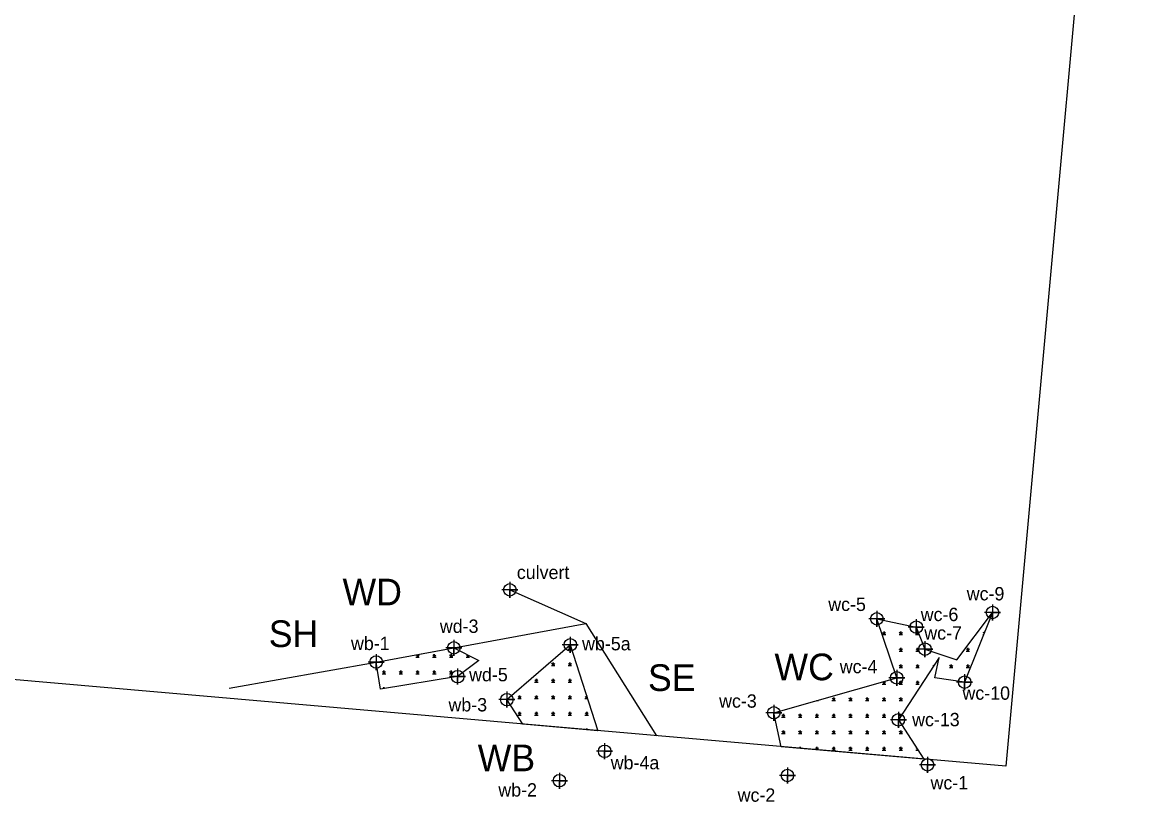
# Model space of a CAD drawing. Extents: x 1637473 to 1644249, y 841388 to 844031.
# Drawn here: x 1643834.8 to 1644249.1, y 841860 to 842152.5 of the extents above; entities that cross this region are included whole.
import ezdxf

# ---------------------------------------------------------------- set-up
doc = ezdxf.new("R2010")
doc.units = 0
for name, color, linetype in [('Default', 7, 'Continuous'), ('Exist Environmental Wetland Boundary', 7, 'Continuous'), ('Exist Environmental Wetland Boundary Cogo Number', 7, 'Continuous'), ('Exist Environmental Wetland Boundary Cogo Point CELL', 7, 'Continuous'), ('Exist Environmental Wetland Boundary Text', 7, 'Continuous'), ('Exist Hydro Jurisdictional Stream or Body of Water Mitigable', 7, 'Continuous'), ('Exist Hydro Jurisdictional Stream or Body of Water Mitigable Cogo Number', 7, 'Continuous'), ('Exist Hydro Jurisdictional Stream or Body of Water Mitigable Cogo Point CELL', 7, 'Continuous'), ('Exist Hydro Jurisdictional Stream or Body of Water Mitigable Text', 7, 'Continuous')]:
    doc.layers.add(name, color=color, linetype=linetype)

msp = doc.modelspace()

# ---------------------------------------------------------------- linework, layer by layer
at = {"layer": 'Default'}
msp.add_lwpolyline([(1643420.44, 842444.99), (1644249.14, 842372.65), (1644203.72, 841873.41), (1643376.84, 841945.6)], dxfattribs=at)
at = {"layer": 'Exist Environmental Wetland Boundary'}
for points in [[(1644198.76, 841931.06), (1644188.29, 841904.96), (1644177.17, 841906.58), (1644178.79, 841914.22), (1644163.45, 841890.81), (1644172.99, 841876.09), (1644119.48, 841880.76), (1644116.71, 841893.48), (1644162.8, 841906.58), (1644155.38, 841928.73), (1644170.15, 841925.61), (1644173.42, 841917.33), (1644185.39, 841913.29)], [(1644040.4, 841918.96), (1644050.78, 841886.76), (1644022.57, 841889.22), (1644016.62, 841898.41)], [(1643998.17, 841907.02), (1643969.25, 841902.37), (1643967.6, 841912.49), (1643996.74, 841917.83), (1644006.11, 841913.03)]]:
    msp.add_lwpolyline(points, close=True, dxfattribs=at)
at = {"layer": 'Exist Environmental Wetland Boundary Cogo Point CELL'}
for points in [[(1644155.38, 841931.73), (1644155.38, 841925.73), (1644155.38, 841928.73), (1644158.38, 841928.73), (1644152.38, 841928.73)], [(1644198.76, 841934.06), (1644198.76, 841928.06), (1644198.76, 841931.06), (1644201.76, 841931.06), (1644195.76, 841931.06)], [(1644170.15, 841928.61), (1644170.15, 841922.61), (1644170.15, 841925.61), (1644173.15, 841925.61), (1644167.15, 841925.61)], [(1643996.72, 841920.84), (1643996.72, 841914.84), (1643996.72, 841917.84), (1643999.72, 841917.84), (1643993.72, 841917.84)], [(1644040.4, 841921.96), (1644040.4, 841915.96), (1644040.4, 841918.96), (1644043.4, 841918.96), (1644037.4, 841918.96)], [(1644173.42, 841920.33), (1644173.42, 841914.33), (1644173.42, 841917.33), (1644176.42, 841917.33), (1644170.42, 841917.33)], [(1643967.6, 841915.49), (1643967.6, 841909.49), (1643967.6, 841912.49), (1643970.6, 841912.49), (1643964.6, 841912.49)], [(1643998.17, 841910.02), (1643998.17, 841904.02), (1643998.17, 841907.02), (1644001.17, 841907.02), (1643995.17, 841907.02)], [(1644162.8, 841909.58), (1644162.8, 841903.58), (1644162.8, 841906.58), (1644165.8, 841906.58), (1644159.8, 841906.58)], [(1644188.29, 841907.96), (1644188.29, 841901.96), (1644188.29, 841904.96), (1644191.29, 841904.96), (1644185.29, 841904.96)], [(1644016.62, 841901.41), (1644016.62, 841895.41), (1644016.62, 841898.41), (1644019.62, 841898.41), (1644013.62, 841898.41)], [(1644116.71, 841896.48), (1644116.71, 841890.48), (1644116.71, 841893.48), (1644119.71, 841893.48), (1644113.71, 841893.48)], [(1644163.45, 841893.81), (1644163.45, 841887.81), (1644163.45, 841890.81), (1644166.45, 841890.81), (1644160.45, 841890.81)], [(1644053.27, 841882.02), (1644053.27, 841876.02), (1644053.27, 841879.02), (1644056.27, 841879.02), (1644050.27, 841879.02)], [(1644174.37, 841876.97), (1644174.37, 841870.97), (1644174.37, 841873.97), (1644177.37, 841873.97), (1644171.37, 841873.97)], [(1644036.33, 841870.99), (1644036.33, 841864.99), (1644036.33, 841867.99), (1644039.33, 841867.99), (1644033.33, 841867.99)], [(1644121.83, 841872.93), (1644121.83, 841866.93), (1644121.83, 841869.93), (1644124.83, 841869.93), (1644118.83, 841869.93)]]:
    msp.add_lwpolyline(points, dxfattribs=at)
for centre in [(1644155.38, 841928.73), (1644198.76, 841931.06), (1644170.15, 841925.61), (1643996.72, 841917.84), (1644040.4, 841918.96), (1644173.42, 841917.33), (1643967.6, 841912.49), (1643998.17, 841907.02), (1644162.8, 841906.58), (1644188.29, 841904.96), (1644016.62, 841898.41), (1644116.71, 841893.48), (1644163.45, 841890.81), (1644053.27, 841879.02), (1644174.37, 841873.97), (1644036.33, 841867.99), (1644121.83, 841869.93)]:
    msp.add_circle(centre, 2.34, dxfattribs=at)
at = {"layer": 'Exist Hydro Jurisdictional Stream or Body of Water Mitigable'}
for p, q in [((1644195.15, 841922.78), (1644195.44, 841922.78)), ((1644176.28, 841910.42), (1644176.3, 841910.42)), ((1644163.7, 841891.87), (1644164.14, 841891.87))]:
    msp.add_line(p, q, dxfattribs=at)
for points in [[(1644017.71, 841939.6), (1644046.25, 841926.95), (1644072.77, 841884.84)], [(1643912.46, 841902.74), (1643967.6, 841912.49), (1644046.25, 841926.95)], [(1644157.41, 841922.78), (1644158.06, 841922.78), (1644158.06, 841923.97), (1644158.06, 841922.78), (1644158.7, 841922.78)], [(1644163.7, 841922.78), (1644164.35, 841922.78), (1644164.35, 841923.97), (1644164.35, 841922.78), (1644164.99, 841922.78)], [(1644169.99, 841922.78), (1644170.64, 841922.78), (1644170.64, 841923.97), (1644170.64, 841922.78), (1644171.27, 841922.78)], [(1644195.8, 841923.68), (1644195.8, 841923.97), (1644195.8, 841923.68)], [(1643982.47, 841914.31), (1643983.12, 841914.31), (1643983.12, 841915.34)], [(1643983.12, 841915.34), (1643983.12, 841914.31), (1643983.76, 841914.31)], [(1643988.76, 841914.31), (1643989.41, 841914.31), (1643989.41, 841915.49), (1643989.41, 841914.31), (1643990.05, 841914.31)], [(1643995.05, 841914.31), (1643995.7, 841914.31), (1643995.7, 841915.49), (1643995.7, 841914.31), (1643996.34, 841914.31)], [(1644001.34, 841914.31), (1644001.99, 841914.31), (1644001.99, 841915.14)], [(1644001.99, 841915.14), (1644001.99, 841914.31), (1644002.63, 841914.31)], [(1644039.62, 841917.33), (1644040.26, 841917.33), (1644040.26, 841918.52), (1644040.26, 841917.33), (1644040.91, 841917.33)], [(1644163.7, 841916.6), (1644164.35, 841916.6), (1644164.35, 841917.78), (1644164.35, 841916.6), (1644164.99, 841916.6)], [(1644169.99, 841916.6), (1644170.64, 841916.6), (1644170.64, 841917.78), (1644170.64, 841916.6), (1644171.28, 841916.6)], [(1644188.86, 841916.6), (1644189.51, 841916.6), (1644189.51, 841917.78), (1644189.51, 841916.6), (1644190.15, 841916.6)], [(1644033.33, 841911.15), (1644033.97, 841911.15), (1644033.97, 841912.33), (1644033.97, 841911.15), (1644034.62, 841911.15)], [(1644039.62, 841911.15), (1644040.26, 841911.15), (1644040.26, 841912.33), (1644040.26, 841911.15), (1644040.91, 841911.15)], [(1644163.7, 841910.42), (1644164.35, 841910.42), (1644164.35, 841911.6), (1644164.35, 841910.42), (1644164.99, 841910.42)], [(1644169.99, 841910.42), (1644170.64, 841910.42), (1644170.64, 841911.6), (1644170.64, 841910.42), (1644171.28, 841910.42)], [(1644176.93, 841911.38), (1644176.93, 841911.6), (1644176.93, 841911.38)], [(1644182.57, 841910.42), (1644183.22, 841910.42), (1644183.22, 841911.6), (1644183.22, 841910.42), (1644183.86, 841910.42)], [(1644188.86, 841910.42), (1644189.51, 841910.42), (1644189.51, 841911.6), (1644189.51, 841910.42), (1644190.15, 841910.42)], [(1643969.89, 841908.12), (1643970.54, 841908.12), (1643970.54, 841909.31), (1643970.54, 841908.12), (1643971.18, 841908.12)], [(1643976.18, 841908.12), (1643976.83, 841908.12), (1643976.83, 841909.31), (1643976.83, 841908.12), (1643977.47, 841908.12)], [(1643982.47, 841908.12), (1643983.12, 841908.12), (1643983.12, 841909.31), (1643983.12, 841908.12), (1643983.76, 841908.12)], [(1643988.76, 841908.12), (1643989.41, 841908.12), (1643989.41, 841909.31), (1643989.41, 841908.12), (1643990.05, 841908.12)], [(1643995.05, 841908.12), (1643995.7, 841908.12), (1643995.7, 841909.31), (1643995.7, 841908.12), (1643996.34, 841908.12)], [(1644027.04, 841904.97), (1644027.68, 841904.97), (1644027.68, 841906.15), (1644027.68, 841904.97), (1644028.33, 841904.97)], [(1644033.33, 841904.97), (1644033.97, 841904.97), (1644033.97, 841906.15), (1644033.97, 841904.97), (1644034.62, 841904.97)], [(1644039.62, 841904.97), (1644040.26, 841904.97), (1644040.26, 841906.15), (1644040.26, 841904.97), (1644040.91, 841904.97)], [(1643970.54, 841902.57), (1643970.54, 841903.12), (1643970.54, 841902.57)], [(1644157.41, 841904.23), (1644158.06, 841904.23), (1644158.06, 841905.24)], [(1644158.06, 841905.24), (1644158.06, 841904.23), (1644158.7, 841904.23)], [(1644163.7, 841904.23), (1644164.35, 841904.23), (1644164.35, 841905.42), (1644164.35, 841904.23), (1644164.99, 841904.23)], [(1644169.99, 841904.23), (1644170.64, 841904.23), (1644170.64, 841905.42), (1644170.64, 841904.23), (1644171.28, 841904.23)], [(1644020.75, 841898.78), (1644021.39, 841898.78), (1644021.39, 841899.97), (1644021.39, 841898.78), (1644022.04, 841898.78)], [(1644027.04, 841898.78), (1644027.68, 841898.78), (1644027.68, 841899.97), (1644027.68, 841898.78), (1644028.33, 841898.78)], [(1644033.33, 841898.78), (1644033.97, 841898.78), (1644033.97, 841899.97), (1644033.97, 841898.78), (1644034.62, 841898.78)], [(1644039.62, 841898.78), (1644040.26, 841898.78), (1644040.26, 841899.97), (1644040.26, 841898.78), (1644040.91, 841898.78)], [(1644045.91, 841898.78), (1644046.55, 841898.78), (1644046.55, 841899.87)], [(1644046.55, 841899.87), (1644046.55, 841898.78), (1644046.9, 841898.78)], [(1644132.78, 841898.05), (1644132.9, 841898.05), (1644132.9, 841898.08)], [(1644132.9, 841898.08), (1644132.9, 841898.05), (1644133.54, 841898.05)], [(1644138.54, 841898.05), (1644139.19, 841898.05), (1644139.19, 841899.23), (1644139.19, 841898.05), (1644139.83, 841898.05)], [(1644144.83, 841898.05), (1644145.48, 841898.05), (1644145.48, 841899.23), (1644145.48, 841898.05), (1644146.12, 841898.05)], [(1644151.12, 841898.05), (1644151.77, 841898.05), (1644151.77, 841899.23), (1644151.77, 841898.05), (1644152.41, 841898.05)], [(1644157.41, 841898.05), (1644158.06, 841898.05), (1644158.06, 841899.23), (1644158.06, 841898.05), (1644158.7, 841898.05)], [(1644163.7, 841898.05), (1644164.35, 841898.05), (1644164.35, 841899.23), (1644164.35, 841898.05), (1644164.99, 841898.05)], [(1644020.75, 841892.6), (1644021.39, 841892.6), (1644021.39, 841893.78), (1644021.39, 841892.6), (1644022.04, 841892.6)], [(1644027.04, 841892.6), (1644027.68, 841892.6), (1644027.68, 841893.78), (1644027.68, 841892.6), (1644028.33, 841892.6)], [(1644033.33, 841892.6), (1644033.97, 841892.6), (1644033.97, 841893.78), (1644033.97, 841892.6), (1644034.62, 841892.6)], [(1644039.62, 841892.6), (1644040.26, 841892.6), (1644040.26, 841893.78), (1644040.26, 841892.6), (1644040.91, 841892.6)], [(1644045.91, 841892.6), (1644046.55, 841892.6), (1644046.55, 841893.78), (1644046.55, 841892.6), (1644047.2, 841892.6)], [(1644119.67, 841891.87), (1644120.32, 841891.87), (1644120.32, 841893.05), (1644120.32, 841891.87), (1644120.96, 841891.87)], [(1644125.96, 841891.87), (1644126.61, 841891.87), (1644126.61, 841893.05), (1644126.61, 841891.87), (1644127.25, 841891.87)], [(1644132.25, 841891.87), (1644132.9, 841891.87), (1644132.9, 841893.05), (1644132.9, 841891.87), (1644133.54, 841891.87)], [(1644138.54, 841891.87), (1644139.19, 841891.87), (1644139.19, 841893.05), (1644139.19, 841891.87), (1644139.83, 841891.87)], [(1644144.83, 841891.87), (1644145.48, 841891.87), (1644145.48, 841893.05), (1644145.48, 841891.87), (1644146.12, 841891.87)], [(1644151.12, 841891.87), (1644151.77, 841891.87), (1644151.77, 841893.05), (1644151.77, 841891.87), (1644152.41, 841891.87)], [(1644157.41, 841891.87), (1644158.06, 841891.87), (1644158.06, 841893.05), (1644158.06, 841891.87), (1644158.7, 841891.87)], [(1644164.35, 841892.18), (1644164.35, 841893.05), (1644164.35, 841892.18)], [(1644046.55, 841887.13), (1644046.55, 841887.6), (1644046.55, 841887.13)], [(1644119.67, 841885.68), (1644120.32, 841885.68), (1644120.32, 841886.87), (1644120.32, 841885.68), (1644120.96, 841885.68)], [(1644125.96, 841885.68), (1644126.61, 841885.68), (1644126.61, 841886.87), (1644126.61, 841885.68), (1644127.25, 841885.68)], [(1644132.25, 841885.68), (1644132.9, 841885.68), (1644132.9, 841886.87), (1644132.9, 841885.68), (1644133.54, 841885.68)], [(1644138.54, 841885.68), (1644139.19, 841885.68), (1644139.19, 841886.87), (1644139.19, 841885.68), (1644139.83, 841885.68)], [(1644144.83, 841885.68), (1644145.48, 841885.68), (1644145.48, 841886.87), (1644145.48, 841885.68), (1644146.12, 841885.68)], [(1644151.12, 841885.68), (1644151.77, 841885.68), (1644151.77, 841886.87), (1644151.77, 841885.68), (1644152.41, 841885.68)], [(1644157.41, 841885.68), (1644158.06, 841885.68), (1644158.06, 841886.87), (1644158.06, 841885.68), (1644158.7, 841885.68)], [(1644163.7, 841885.68), (1644164.35, 841885.68), (1644164.35, 841886.87), (1644164.35, 841885.68), (1644164.99, 841885.68)], [(1644126.61, 841880.14), (1644126.61, 841880.68), (1644126.61, 841880.14)], [(1644132.9, 841879.59), (1644132.9, 841880.68), (1644132.9, 841879.59)], [(1644138.54, 841879.5), (1644139.19, 841879.5), (1644139.19, 841880.68), (1644139.19, 841879.5), (1644139.83, 841879.5)], [(1644144.83, 841879.5), (1644145.48, 841879.5), (1644145.48, 841880.68), (1644145.48, 841879.5), (1644146.12, 841879.5)], [(1644151.12, 841879.5), (1644151.77, 841879.5), (1644151.77, 841880.68), (1644151.77, 841879.5), (1644152.41, 841879.5)], [(1644157.41, 841879.5), (1644158.06, 841879.5), (1644158.06, 841880.68), (1644158.06, 841879.5), (1644158.7, 841879.5)], [(1644163.7, 841879.5), (1644164.35, 841879.5), (1644164.35, 841880.68), (1644164.35, 841879.5), (1644164.99, 841879.5)], [(1644169.99, 841879.5), (1644170.64, 841879.5), (1644170.64, 841879.72)], [(1644170.64, 841879.72), (1644170.64, 841879.5), (1644170.78, 841879.5)]]:
    msp.add_lwpolyline(points, dxfattribs=at)
for centre, radius, start, end in [((1644157.14, 841922.72), 0.922, 4.1403, 67.535), ((1644159.42, 841922.33), 1.44, 122.1274, 161.6222), ((1644163.43, 841922.72), 0.922, 4.1403, 67.535), ((1644165.72, 841922.33), 1.44, 122.1274, 161.6222), ((1644169.72, 841922.72), 0.922, 4.1403, 67.535), ((1644172.01, 841922.33), 1.44, 132.7638, 161.6222), ((1644194.88, 841922.72), 0.922, 35.5083, 67.535), ((1643982.2, 841914.24), 0.922, 4.1403, 67.535), ((1643984.48, 841913.85), 1.44, 122.1274, 161.6222), ((1643988.49, 841914.24), 0.922, 4.1403, 67.535), ((1643990.77, 841913.85), 1.44, 122.1274, 161.6222), ((1643994.78, 841914.24), 0.922, 4.1403, 67.535), ((1643997.06, 841913.85), 1.44, 122.1274, 161.6222), ((1644001.07, 841914.24), 0.922, 4.1403, 67.535), ((1644003.35, 841913.85), 1.44, 131.6641, 161.6222), ((1644039.34, 841917.27), 0.922, 4.1403, 67.535), ((1644041.63, 841916.88), 1.44, 129.625, 161.6222), ((1644163.43, 841916.53), 0.922, 4.1403, 67.535), ((1644165.72, 841916.15), 1.44, 122.1274, 161.6222), ((1644169.72, 841916.53), 0.922, 4.1403, 67.535), ((1644172.01, 841916.15), 1.44, 122.1274, 161.6222), ((1644188.59, 841916.53), 0.922, 4.1403, 67.535), ((1644190.88, 841916.15), 1.44, 122.1274, 161.6222), ((1644033.05, 841911.08), 0.922, 4.1403, 67.535), ((1644035.34, 841910.7), 1.44, 122.1274, 161.6222), ((1644039.34, 841911.08), 0.922, 4.1403, 67.535), ((1644041.63, 841910.7), 1.44, 122.1274, 161.6222), ((1644163.43, 841910.35), 0.922, 4.1403, 67.535), ((1644165.72, 841909.96), 1.44, 122.1274, 161.6222), ((1644169.72, 841910.35), 0.922, 4.1403, 67.535), ((1644172.01, 841909.96), 1.44, 122.1274, 161.6222), ((1644176.01, 841910.35), 0.922, 43.8921, 67.535), ((1644182.3, 841910.35), 0.922, 4.1403, 67.535), ((1644184.59, 841909.96), 1.44, 122.1274, 161.6222), ((1644188.59, 841910.35), 0.922, 4.1403, 67.535), ((1644190.88, 841909.96), 1.44, 122.1274, 161.6222), ((1643969.62, 841908.06), 0.922, 4.1403, 67.535), ((1643971.9, 841907.67), 1.44, 122.1274, 161.6222), ((1643975.91, 841908.06), 0.922, 4.1403, 67.535), ((1643978.19, 841907.67), 1.44, 122.1274, 161.6222), ((1643982.2, 841908.06), 0.922, 4.1403, 67.535), ((1643984.48, 841907.67), 1.44, 122.1274, 161.6222), ((1643988.49, 841908.06), 0.922, 4.1403, 67.535), ((1643990.77, 841907.67), 1.44, 122.1274, 161.6222), ((1643994.78, 841908.06), 0.922, 4.1403, 67.535), ((1643997.06, 841907.67), 1.44, 122.1274, 161.6222), ((1643969.62, 841901.87), 0.922, 45.5037, 67.535), ((1643971.9, 841901.48), 1.44, 122.1274, 125.3576), ((1644026.76, 841904.9), 0.922, 4.1403, 67.535), ((1644029.05, 841904.51), 1.44, 122.1274, 161.6222), ((1644033.05, 841904.9), 0.922, 4.1403, 67.535), ((1644035.34, 841904.51), 1.44, 122.1274, 161.6222), ((1644039.34, 841904.9), 0.922, 4.1403, 67.535), ((1644041.63, 841904.51), 1.44, 122.1274, 161.6222), ((1644157.14, 841904.17), 0.922, 4.1403, 67.535), ((1644159.42, 841903.78), 1.44, 122.1274, 161.6222), ((1644163.43, 841904.17), 0.922, 4.1403, 67.535), ((1644165.72, 841903.78), 1.44, 122.1274, 161.6222), ((1644169.72, 841904.17), 0.922, 4.1403, 67.535), ((1644172.01, 841903.78), 1.44, 122.1274, 161.6222), ((1644020.47, 841898.72), 0.922, 4.1403, 67.535), ((1644022.76, 841898.33), 1.44, 122.1274, 161.6222), ((1644026.76, 841898.72), 0.922, 4.1403, 67.535), ((1644029.05, 841898.33), 1.44, 122.1274, 161.6222), ((1644033.05, 841898.72), 0.922, 4.1403, 67.535), ((1644035.34, 841898.33), 1.44, 122.1274, 161.6222), ((1644039.34, 841898.72), 0.922, 4.1403, 67.535), ((1644041.63, 841898.33), 1.44, 122.1274, 161.6222), ((1644045.63, 841898.72), 0.922, 4.1403, 67.535), ((1644047.92, 841898.33), 1.44, 143.0243, 161.6222), ((1644131.98, 841897.98), 0.922, 4.1403, 6.1685), ((1644134.26, 841897.6), 1.44, 160.0653, 161.6222), ((1644138.27, 841897.98), 0.922, 4.1403, 67.535), ((1644140.55, 841897.6), 1.44, 122.1274, 161.6222), ((1644144.56, 841897.98), 0.922, 4.1403, 67.535), ((1644146.84, 841897.6), 1.44, 122.1274, 161.6222), ((1644150.85, 841897.98), 0.922, 4.1403, 67.535), ((1644153.13, 841897.6), 1.44, 122.1274, 161.6222), ((1644157.14, 841897.98), 0.922, 4.1403, 67.535), ((1644159.42, 841897.6), 1.44, 122.1274, 161.6222), ((1644163.43, 841897.98), 0.922, 4.1403, 67.535), ((1644165.72, 841897.6), 1.44, 122.1274, 161.6222), ((1644020.47, 841892.53), 0.922, 4.1403, 67.535), ((1644022.76, 841892.14), 1.44, 122.1274, 161.6222), ((1644026.76, 841892.53), 0.922, 4.1403, 67.535), ((1644029.05, 841892.14), 1.44, 122.1274, 161.6222), ((1644033.05, 841892.53), 0.922, 4.1403, 67.535), ((1644035.34, 841892.14), 1.44, 122.1274, 161.6222), ((1644039.34, 841892.53), 0.922, 4.1403, 67.535), ((1644041.63, 841892.14), 1.44, 122.1274, 161.6222), ((1644045.63, 841892.53), 0.922, 4.1403, 67.535), ((1644047.92, 841892.14), 1.44, 122.1274, 161.6222), ((1644119.4, 841891.8), 0.922, 4.1403, 67.535), ((1644121.68, 841891.41), 1.44, 122.1274, 161.6222), ((1644125.69, 841891.8), 0.922, 4.1403, 67.535), ((1644127.97, 841891.41), 1.44, 122.1274, 161.6222), ((1644131.98, 841891.8), 0.922, 4.1403, 67.535), ((1644134.26, 841891.41), 1.44, 122.1274, 161.6222), ((1644138.27, 841891.8), 0.922, 4.1403, 67.535), ((1644140.55, 841891.41), 1.44, 122.1274, 161.6222), ((1644144.56, 841891.8), 0.922, 4.1403, 67.535), ((1644146.84, 841891.41), 1.44, 122.1274, 161.6222), ((1644150.85, 841891.8), 0.922, 4.1403, 67.535), ((1644153.13, 841891.41), 1.44, 122.1274, 161.6222), ((1644157.14, 841891.8), 0.922, 4.1403, 67.535), ((1644159.42, 841891.41), 1.44, 122.1274, 161.6222), ((1644163.43, 841891.8), 0.922, 19.1991, 67.535), ((1644045.63, 841886.35), 0.922, 63.0345, 67.535), ((1644047.92, 841885.96), 1.44, 122.1274, 128.6802), ((1644119.4, 841885.62), 0.922, 4.1403, 67.535), ((1644121.68, 841885.23), 1.44, 122.1274, 161.6222), ((1644125.69, 841885.62), 0.922, 4.1403, 67.535), ((1644127.97, 841885.23), 1.44, 122.1274, 161.6222), ((1644131.98, 841885.62), 0.922, 4.1403, 67.535), ((1644134.26, 841885.23), 1.44, 122.1274, 161.6222), ((1644138.27, 841885.62), 0.922, 4.1403, 67.535), ((1644140.55, 841885.23), 1.44, 122.1274, 161.6222), ((1644144.56, 841885.62), 0.922, 4.1403, 67.535), ((1644146.84, 841885.23), 1.44, 122.1274, 161.6222), ((1644150.85, 841885.62), 0.922, 4.1403, 67.535), ((1644153.13, 841885.23), 1.44, 122.1274, 161.6222), ((1644157.14, 841885.62), 0.922, 4.1403, 67.535), ((1644159.42, 841885.23), 1.44, 122.1274, 161.6222), ((1644163.43, 841885.62), 0.922, 4.1403, 67.535), ((1644165.72, 841885.23), 1.44, 122.1274, 161.6222), ((1644125.69, 841879.43), 0.922, 52.994, 67.535), ((1644127.97, 841879.05), 1.44, 122.1274, 132.7498), ((1644131.98, 841879.43), 0.922, 9.77, 67.535), ((1644134.26, 841879.05), 1.44, 122.1274, 157.9712), ((1644138.27, 841879.43), 0.922, 4.1403, 67.535), ((1644140.55, 841879.05), 1.44, 122.1274, 161.6222), ((1644144.56, 841879.43), 0.922, 4.1403, 67.535), ((1644146.84, 841879.05), 1.44, 122.1274, 161.6222), ((1644150.85, 841879.43), 0.922, 4.1403, 67.535), ((1644153.13, 841879.05), 1.44, 122.1274, 161.6222), ((1644157.14, 841879.43), 0.922, 4.1403, 67.535), ((1644159.42, 841879.05), 1.44, 122.1274, 161.6222), ((1644163.43, 841879.43), 0.922, 4.1403, 67.535), ((1644165.72, 841879.05), 1.44, 122.1274, 161.6222), ((1644169.72, 841879.43), 0.922, 4.1403, 67.535), ((1644172.01, 841879.05), 1.44, 155.6527, 161.6222)]:
    msp.add_arc(centre, radius, start, end, dxfattribs=at)
at = {"layer": 'Exist Hydro Jurisdictional Stream or Body of Water Mitigable Cogo Point CELL'}
msp.add_lwpolyline([(1644017.71, 841942.6), (1644017.71, 841936.6), (1644017.71, 841939.6), (1644020.71, 841939.6), (1644014.71, 841939.6)], dxfattribs=at)
msp.add_circle((1644017.71, 841939.6), 2.34, dxfattribs=at)

# ---------------------------------------------------------------- texts
at = {"layer": 'Exist Environmental Wetland Boundary Cogo Number'}
for s, p in [('wc-9', (1644189.08, 841935.62)), ('wc-5', (1644137.14, 841931.65)), ('wc-6', (1644171.81, 841927.86)), ('wd-3', (1643991.49, 841923.44)), ('wc-7', (1644173.15, 841920.9)), ('wb-1', (1643958.16, 841916.99)), ('wb-5a', (1644044.82, 841916.89)), ('wd-5', (1644002.46, 841905.27)), ('wc-4', (1644141.45, 841908.3)), ('wc-10', (1644187.47, 841898.36)), ('wb-3', (1643994.72, 841893.98)), ('wc-3', (1644096.21, 841895.38)), ('wc-13', (1644168.59, 841888.43)), ('wb-4a', (1644055.57, 841872.26)), ('wc-1', (1644175.49, 841864.73)), ('wb-2', (1644013.42, 841862.05)), ('wc-2', (1644103.17, 841860.11))]:
    msp.add_text(s, height=5, dxfattribs=at).set_placement(p)
at = {"layer": 'Exist Environmental Wetland Boundary Text'}
for s, p in [('WD', (1643954.99, 841933.77)), ('WC', (1644116.97, 841905.68)), ('WB', (1644005.68, 841871.54))]:
    msp.add_text(s, height=10, dxfattribs=at).set_placement(p)
at = {"layer": 'Exist Hydro Jurisdictional Stream or Body of Water Mitigable Cogo Number'}
msp.add_text('culvert', height=5, dxfattribs=at).set_placement((1644020.36, 841943.64))
at = {"layer": 'Exist Hydro Jurisdictional Stream or Body of Water Mitigable Text'}
for s, p in [('SH', (1643927.33, 841918.12)), ('SE', (1644069.54, 841901.65))]:
    msp.add_text(s, height=10, dxfattribs=at).set_placement(p)

doc.saveas('drawing.dxf')
